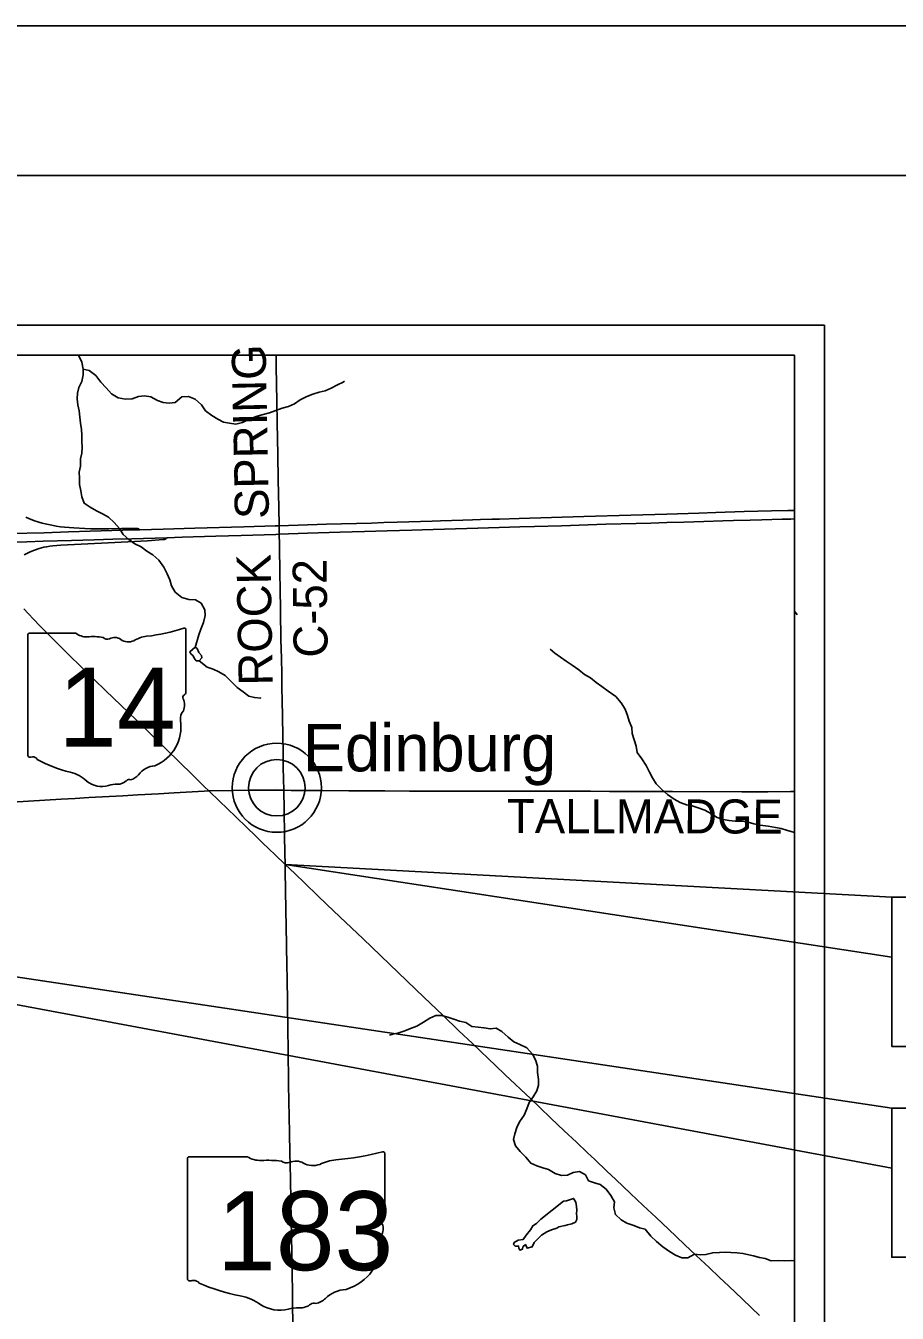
# Model space of a CAD drawing. Extents: x 25.6 to 80.6, y 0.2 to 24.5.
# Drawn here: x 41.848 to 44.756, y 17.932 to 22.23 of the extents above; entities that cross this region are included whole.
import ezdxf

# ---------------------------------------------------------------- set-up
doc = ezdxf.new("R2010")
doc.units = 0
for name, color, linetype in [('GM_X_County_Road', 7, 'Continuous'), ('GM_X_County_Road_Text', 7, 'Continuous'), ('GM_X_Interchange_Ramps', 7, 'Continuous'), ('GM_X_Interstate_Route', 7, 'Continuous'), ('GM_X_Minor_Lake', 7, 'Continuous'), ('GM_X_Minor_River', 7, 'Continuous'), ('GM_X_State_Location', 7, 'Continuous'), ('GM_X_State_Route', 7, 'Continuous'), ('GM_X_State_Shield', 7, 'Continuous'), ('GM_X_Township_Road', 7, 'Continuous'), ('GM_X_Unincorporated', 7, 'Continuous'), ('GM_X_Unincorporated_Location', 7, 'Continuous'), ('GM_X_Unincorporated_Text', 7, 'Continuous'), ('SH_Border', 7, 'Continuous'), ('SH_Cut_Line', 7, 'Continuous'), ('SH_Data', 7, 'Continuous'), ('SH_Text', 7, 'Continuous')]:
    doc.layers.add(name, color=color, linetype=linetype)

msp = doc.modelspace()

# ---------------------------------------------------------------- linework, layer by layer
at = {"layer": 'GM_X_County_Road'}
for points in [[(42.7086, 19.6775), (42.7071, 19.7535), (42.7061, 19.8066), (42.7053, 19.8617), (42.7031, 19.9802), (42.7024, 20.0158), (42.7018, 20.0667), (42.701, 20.1175), (42.6994, 20.1806), (42.6981, 20.2753), (42.6961, 20.3549), (42.6956, 20.3971), (42.6941, 20.4977), (42.6938, 20.5322), (42.6938, 20.5387), (42.6933, 20.5611), (42.6921, 20.622), (42.6898, 20.7139), (42.6887, 20.7971), (42.6879, 20.852), (42.6868, 20.904), (42.6857, 20.9761), (42.6836, 21.093), (42.6832, 21.1303)], [(41.0437, 19.5951), (41.144, 19.6006), (41.1874, 19.603), (41.2197, 19.6047), (41.3686, 19.6136), (41.4381, 19.6175), (41.5399, 19.623), (41.6256, 19.6272), (41.6528, 19.6291), (41.8018, 19.6381), (41.9656, 19.6477), (42.0127, 19.6503), (42.0586, 19.653), (42.1716, 19.6592), (42.2212, 19.6621), (42.2907, 19.6661), (42.3428, 19.6688), (42.443, 19.6746), (42.459, 19.6756)], [(42.459, 19.6756), (42.5364, 19.6767), (42.5926, 19.6776), (42.6484, 19.6777), (42.7086, 19.6775)], [(42.7086, 19.6775), (42.7329, 19.6774), (42.7748, 19.677), (42.8373, 19.6767), (42.9257, 19.6763), (43.046, 19.6756), (43.1282, 19.6752), (43.1941, 19.6751), (43.2986, 19.675), (43.3831, 19.675), (43.4801, 19.6748), (43.5522, 19.6746), (43.618, 19.6744), (43.7324, 19.6743), (43.7958, 19.6741), (43.8678, 19.6739), (43.9276, 19.6739), (44.0059, 19.6732), (44.2371, 19.6729), (44.3241, 19.673), (44.3999, 19.6731), (44.4128, 19.6732)], [(42.7128, 19.4303), (42.7119, 19.4689), (42.7106, 19.525), (42.7101, 19.6121), (42.7086, 19.6775)]]:
    msp.add_lwpolyline(points, dxfattribs=at)
at = {"layer": 'GM_X_Interchange_Ramps'}
for points in [[(42.2286, 20.5475), (42.2265, 20.5494), (42.2249, 20.5503), (42.2231, 20.551), (42.2211, 20.5514), (42.2192, 20.5516), (42.2149, 20.5519), (42.2036, 20.552), (42.1671, 20.5517), (42.1244, 20.551), (42.0834, 20.5507), (42.0648, 20.551), (42.0449, 20.5517), (42.0076, 20.5537), (41.9922, 20.5549), (41.9766, 20.5564), (41.9635, 20.5577), (41.9495, 20.5597), (41.9348, 20.5623), (41.9236, 20.5647), (41.9129, 20.567), (41.9025, 20.5697), (41.8914, 20.573), (41.8845, 20.5752), (41.8772, 20.5777), (41.8687, 20.5809), (41.8598, 20.5842), (41.8474, 20.5895)], [(41.8425, 20.4636), (41.8494, 20.4673), (41.8558, 20.4705), (41.8629, 20.4738), (41.8767, 20.4794), (41.8919, 20.4846), (41.9004, 20.4871), (41.9084, 20.489), (41.9175, 20.491), (41.9277, 20.4926), (41.9382, 20.4939), (41.9512, 20.4953), (41.9642, 20.4961), (42.1231, 20.5042), (42.2534, 20.5105), (42.3066, 20.5145), (42.3089, 20.5149), (42.3111, 20.5155), (42.3127, 20.5161), (42.3147, 20.5171), (42.3158, 20.5178), (42.3169, 20.5188), (42.3183, 20.521)]]:
    msp.add_lwpolyline(points, dxfattribs=at)
at = {"layer": 'GM_X_Interstate_Route'}
for points in [[(41.7951, 20.5346), (41.9095, 20.5377), (41.9902, 20.5402), (42.0623, 20.5424), (42.1717, 20.5457), (42.2286, 20.5475), (42.3059, 20.5499), (42.4115, 20.5528), (42.5756, 20.5576), (42.6799, 20.5607), (42.6933, 20.5611), (42.8514, 20.5659), (43.0018, 20.57), (43.0428, 20.5713), (43.0875, 20.5725), (43.2043, 20.5762), (43.2317, 20.5772), (43.3062, 20.5797), (43.3385, 20.5805), (43.3646, 20.5814), (43.4031, 20.5824), (43.428, 20.5832), (43.4938, 20.5851), (43.6019, 20.5883), (43.71, 20.5917), (43.8666, 20.5964), (43.9872, 20.5999), (44.094, 20.6029), (44.15, 20.6047), (44.245, 20.6079), (44.3362, 20.6106), (44.3909, 20.6116), (44.4128, 20.6119)], [(41.7838, 20.5054), (41.8509, 20.5074), (41.9056, 20.5091), (42, 20.5116), (42.0758, 20.5141), (42.138, 20.5159), (42.2014, 20.5176), (42.3183, 20.521), (42.3691, 20.5228), (42.4064, 20.5239), (42.4824, 20.5261), (42.567, 20.5286), (42.6823, 20.5318), (42.6938, 20.5322), (42.7878, 20.5358), (42.896, 20.5393), (42.978, 20.5414), (43.0538, 20.5436), (43.1358, 20.5463), (43.1706, 20.5473), (43.3557, 20.5526), (43.4278, 20.5548), (43.4962, 20.5567), (43.5458, 20.5584), (43.6353, 20.5611), (43.7832, 20.5657), (43.8851, 20.5685), (43.9336, 20.5697), (43.987, 20.5714), (44.0442, 20.5733), (44.0765, 20.5742), (44.11, 20.5753), (44.1734, 20.5769), (44.2094, 20.5779), (44.2654, 20.5797), (44.3039, 20.5808), (44.3722, 20.5826), (44.4008, 20.5833), (44.4128, 20.5834)]]:
    msp.add_lwpolyline(points, dxfattribs=at)
at = {"layer": 'GM_X_Minor_Lake'}
for p, q in [((42.3983, 20.1335), (42.4061, 20.1261)), ((43.642, 18.3061), (43.5662, 18.2459))]:
    msp.add_line(p, q, dxfattribs=at)
for points in [[(42.4061, 20.1261), (42.4099, 20.1192), (42.4168, 20.1102), (42.4266, 20.1103), (42.4356, 20.1203), (42.434, 20.1279), (42.4256, 20.1377), (42.4193, 20.1513), (42.4125, 20.155), (42.3952, 20.1396), (42.3983, 20.1335)], [(43.5662, 18.2459), (43.552, 18.2312), (43.54, 18.2235), (43.5318, 18.2097), (43.5176, 18.1921), (43.5079, 18.1783), (43.4913, 18.1758), (43.477, 18.1673), (43.4756, 18.1612), (43.4809, 18.1551), (43.4923, 18.156), (43.4931, 18.1485), (43.4962, 18.1424), (43.5053, 18.1456), (43.5067, 18.1532), (43.515, 18.1609), (43.5204, 18.1488), (43.5378, 18.1536), (43.5444, 18.1681), (43.5594, 18.1835), (43.5691, 18.1927), (43.5864, 18.2036), (43.6022, 18.2106), (43.6196, 18.2161), (43.6264, 18.22), (43.6475, 18.2248), (43.6558, 18.2265), (43.6702, 18.2297), (43.6822, 18.2359), (43.6867, 18.2443), (43.6866, 18.2534), (43.6857, 18.2641), (43.6863, 18.2755), (43.6854, 18.2884), (43.6837, 18.3028), (43.676, 18.3148), (43.6526, 18.3069), (43.642, 18.3061)]]:
    msp.add_lwpolyline(points, dxfattribs=at)
at = {"layer": 'GM_X_Minor_River'}
for points in [[(42.0234, 21.1303), (42.0352, 21.1067), (42.0393, 21.0832), (42.0395, 21.0643), (42.0345, 21.0429), (42.0249, 21.023), (42.0205, 21.004), (42.0193, 20.985), (42.0218, 20.9645), (42.0258, 20.9448), (42.0276, 20.9236), (42.0301, 20.9038), (42.0341, 20.8826), (42.0343, 20.8636), (42.0353, 20.8431), (42.0364, 20.8219), (42.0351, 20.8029), (42.0308, 20.7838), (42.0303, 20.7603), (42.026, 20.7397), (42.027, 20.7192), (42.0272, 20.6987), (42.0313, 20.6775), (42.0345, 20.6578), (42.0424, 20.6358), (42.063, 20.6224), (42.0836, 20.6105), (42.1034, 20.6009), (42.124, 20.5897), (42.1431, 20.5717), (42.1608, 20.5514), (42.1724, 20.5318), (42.1915, 20.5146), (42.2122, 20.5004), (42.2327, 20.49), (42.2518, 20.4759), (42.2717, 20.4639), (42.2923, 20.446), (42.3085, 20.4226), (42.3194, 20.4007), (42.328, 20.3803), (42.3343, 20.3606), (42.3459, 20.3395), (42.3688, 20.3208), (42.3916, 20.315), (42.4136, 20.313), (42.4327, 20.3026), (42.4458, 20.28), (42.4468, 20.261), (42.441, 20.2374), (42.4314, 20.216), (42.4256, 20.1969), (42.4134, 20.1545)], [(42.0393, 21.0832), (42.0598, 21.0797), (42.0812, 21.0625), (42.0981, 21.0407), (42.1158, 21.0211), (42.1342, 21.0009), (42.1556, 20.9874), (42.1806, 20.984), (42.2026, 20.985), (42.2237, 20.9921), (42.2441, 20.9946), (42.2654, 20.9911), (42.2875, 20.9785), (42.3065, 20.9726), (42.3262, 20.9698), (42.3459, 20.9723), (42.3684, 20.9909), (42.3903, 20.9919), (42.4132, 20.9831), (42.4346, 20.9651), (42.4477, 20.9448), (42.4684, 20.9291), (42.4882, 20.9164), (42.508, 20.9068), (42.5278, 20.9032), (42.5482, 20.9004), (42.5709, 20.906), (42.595, 20.9177), (42.6199, 20.9271), (42.6395, 20.9327), (42.6607, 20.9375), (42.6825, 20.9454), (42.7029, 20.9533), (42.724, 20.9588), (42.7444, 20.9674), (42.7639, 20.9814), (42.7858, 20.9923), (42.8054, 21.0001), (42.8265, 21.0065), (42.8469, 21.0113), (42.8665, 21.0206), (42.8876, 21.0308), (42.9071, 21.0401), (42.9109, 21.0432)], [(44.4128, 19.5373), (44.4098, 19.538), (44.39, 19.5438), (44.368, 19.5496), (44.349, 19.5539), (44.3254, 19.5574), (44.2989, 19.5609), (44.2769, 19.5652), (44.2579, 19.571), (44.2381, 19.5746), (44.2154, 19.575), (44.1949, 19.5763), (44.1744, 19.5806), (44.1554, 19.5872), (44.1356, 19.5991), (44.1142, 19.6118), (44.0914, 19.6191), (44.0716, 19.6257), (44.0527, 19.6292), (44.0313, 19.6373), (44.0115, 19.6477), (43.9894, 19.6634), (43.9702, 19.6806), (43.9511, 19.6994), (43.9395, 19.719), (43.9294, 19.7386), (43.9185, 19.7605), (43.9031, 19.7831), (43.8877, 19.8042), (43.8844, 19.8246), (43.8774, 19.8458), (43.8718, 19.867), (43.87, 19.8875), (43.8615, 19.9079), (43.8559, 19.9276), (43.8481, 19.948), (43.8342, 19.9699), (43.8165, 19.9909), (43.7913, 20.0081), (43.7699, 20.0245), (43.7508, 20.0372), (43.7317, 20.0529), (43.7127, 20.0641), (43.6928, 20.0798), (43.6714, 20.0955), (43.6515, 20.1089), (43.6133, 20.1358), (43.598, 20.1485)], [(42.4266, 20.1103), (42.4534, 20.0886), (42.4732, 20.0821), (42.4922, 20.0732), (42.5128, 20.0605), (42.5534, 20.0208), (42.5733, 20.0058), (42.5924, 19.9916), (42.6114, 19.9873), (42.6319, 19.9853), (42.6296, 19.9875)], [(43.3571, 18.8867), (43.3366, 18.8887), (43.316, 18.9021), (43.2955, 18.9072), (43.2757, 18.9138), (43.2559, 18.9204), (43.2354, 18.9254), (43.2157, 18.9252), (43.1961, 18.9166), (43.1751, 18.9034), (43.1525, 18.8902), (43.1321, 18.8824), (43.1125, 18.8745), (43.0929, 18.8682), (43.0725, 18.8634), (43.062, 18.8595)], [(44.4128, 18.1068), (44.4034, 18.1074), (44.3799, 18.1071), (44.3587, 18.1076), (44.3352, 18.1065), (44.3147, 18.1139), (44.2957, 18.1182), (44.2759, 18.1233), (44.241, 18.1312), (44.2213, 18.1332), (44.2008, 18.1345), (44.1818, 18.1358), (44.1622, 18.1348), (44.1402, 18.1337), (44.1176, 18.1274), (44.0979, 18.1271), (44.0789, 18.1284), (44.0571, 18.1168), (44.0366, 18.1165), (44.0161, 18.1254), (43.9955, 18.138), (43.9733, 18.1537), (43.9527, 18.1709), (43.9335, 18.1889), (43.9143, 18.2122), (43.8953, 18.2165), (43.8763, 18.2247), (43.8534, 18.2327), (43.8344, 18.2439), (43.8152, 18.2611), (43.8097, 18.2838), (43.8125, 18.3036), (43.8001, 18.3247), (43.7847, 18.3458), (43.7648, 18.3615), (43.7458, 18.3666), (43.726, 18.374), (43.7152, 18.3936), (43.6954, 18.4047), (43.6749, 18.4014), (43.6553, 18.3928), (43.6357, 18.3911), (43.6144, 18.3984), (43.5922, 18.4118), (43.5732, 18.4169), (43.5527, 18.4235), (43.5329, 18.4323), (43.5168, 18.4526), (43.4976, 18.4714), (43.4815, 18.4909), (43.4752, 18.5114), (43.4795, 18.5304), (43.486, 18.5518), (43.4957, 18.5709), (43.5113, 18.5931), (43.5194, 18.6145), (43.5275, 18.6351), (43.5409, 18.6542), (43.5535, 18.6742), (43.5586, 18.6932), (43.5591, 18.7122), (43.5558, 18.735), (43.5556, 18.757), (43.5492, 18.7774), (43.5392, 18.797), (43.52, 18.8181), (43.4964, 18.8284), (43.4766, 18.838), (43.4574, 18.8538), (43.4368, 18.8725), (43.4177, 18.8829), (43.398, 18.8811), (43.3768, 18.8847), (43.3571, 18.8867)]]:
    msp.add_lwpolyline(points, dxfattribs=at)
at = {"layer": 'GM_X_State_Route'}
for points in [[(41.8408, 20.2836), (41.8564, 20.2671), (41.8734, 20.2492), (41.8956, 20.2258), (41.9209, 20.2004), (41.9694, 20.1517)], [(41.9694, 20.1517), (41.9951, 20.126), (42.0289, 20.0929), (42.0775, 20.0465), (42.1143, 20.0113), (42.2169, 19.9118), (42.2198, 19.9091)], [(42.2198, 19.9091), (42.3095, 19.8216), (42.3671, 19.7649), (42.3958, 19.7373), (42.4389, 19.6952)], [(42.4389, 19.6952), (42.4447, 19.6896), (42.459, 19.6756), (42.4953, 19.64), (42.5185, 19.6175), (42.5831, 19.5555), (42.6162, 19.5236), (42.6379, 19.5027)], [(42.6379, 19.5027), (42.6799, 19.4625), (42.7128, 19.4303)], [(42.7128, 19.4303), (42.7453, 19.3995), (42.7802, 19.3659), (42.8214, 19.3262), (42.8527, 19.296), (42.8959, 19.2548), (42.9737, 19.1814), (43.0902, 19.0695), (43.1771, 18.9858), (43.2389, 18.9264), (43.293, 18.875), (43.3382, 18.8324), (43.3641, 18.8073), (43.3918, 18.781)], [(42.7406, 17.7303), (42.7405, 17.7348), (42.7396, 17.7946), (42.7387, 17.8812), (42.7378, 17.976), (42.7363, 18.0903), (42.7345, 18.1848), (42.7325, 18.3068), (42.7307, 18.3811), (42.7294, 18.4657), (42.7275, 18.534), (42.7248, 18.6943), (42.7233, 18.8161), (42.7222, 18.8744), (42.7208, 18.9664), (42.7195, 19.0521), (42.7188, 19.0882), (42.7177, 19.1628), (42.716, 19.2796), (42.7133, 19.4075), (42.7128, 19.4303)], [(43.3918, 18.781), (43.4137, 18.7603), (43.4479, 18.7277), (43.5331, 18.6477), (43.5634, 18.6183), (43.5998, 18.5826), (43.6444, 18.5411), (43.6852, 18.5029), (43.722, 18.4676), (43.7464, 18.4446), (43.787, 18.4063), (43.8169, 18.3782), (43.8653, 18.3318), (43.9079, 18.2918), (43.9514, 18.2509), (43.9921, 18.2126), (44.0463, 18.1614), (44.0851, 18.1246), (44.1277, 18.0846), (44.1629, 18.0513), (44.1937, 18.0223), (44.2387, 17.9795), (44.2691, 17.9501), (44.2962, 17.9245)]]:
    msp.add_lwpolyline(points, dxfattribs=at)
at = {"layer": 'GM_X_State_Shield'}
for p, q in [((42.382, 20.0032), (42.382, 20.2126)), ((41.8547, 20.1958), (41.8547, 19.7955)), ((42.0143, 20.2027), (41.8599, 20.2027)), ((42.382, 20.0033), (42.382, 20.0032)), ((42.387, 18.4473), (42.387, 18.0471)), ((42.5865, 18.4542), (42.3935, 18.4542)), ((43.0462, 18.2547), (43.0462, 18.4641)), ((43.0461, 18.2548), (43.0462, 18.2547))]:
    msp.add_line(p, q, dxfattribs=at)
for centre, radius, start, end in [((42.1942, 20.7483), 0.5592, 275.8445, 288.9065), ((42.3762, 20.2135), 0.00587, 351.8621, 97.738), ((41.8607, 20.1966), 0.00611, 98.1301, 188.1301), ((42.0511, 20.2491), 0.0593, 231.6195, 271.1119), ((42.0708, 19.978), 0.2127, 80.4867, 94.9883), ((42.119, 20.1987), 0.0171, 219.7921, 297.1024), ((42.1441, 20.1524), 0.0355, 54.4667, 119.1411), ((42.19, 20.2159), 0.0428, 233.8562, 294.8282), ((42.2655, 20.0804), 0.1125, 97.3462, 120.7689), ((42.3807, 19.9878), 0.00909, 107.944, 210.337), ((42.3758, 20.0024), 0.00628, 289.6038, 7.7341), ((42.3229, 19.9614), 0.0545, 340.033, 23.6496), ((42.2255, 19.889), 0.1399, 292.3089, 8.9858), ((42.4031, 19.9156), 0.0397, 136.8065, 186.9296), ((41.8608, 19.7947), 0.00616, 171.9584, 258.3066), ((41.8617, 19.8356), 0.047, 267.339, 280.6039), ((41.8714, 19.7724), 0.017, 29.7484, 93.2717), ((42.0855, 20.132), 0.4038, 240.4129, 257.1985), ((41.9651, 19.6157), 0.1264, 47.1842, 75.836), ((42.2845, 19.6832), 0.0766, 94.4031, 142.5768), ((42.1017, 19.7705), 0.0802, 230.7004, 286.2918), ((42.1481, 19.6321), 0.0659, 85.6951, 111.2099), ((42.1539, 19.7405), 0.0427, 268.777, 315.5493), ((42.1926, 19.7017), 0.012, 65.7517, 132.6484), ((42.1874, 19.7567), 0.0452, 282.8732, 323.2771)]:
    msp.add_arc(centre, radius, start, end, dxfattribs=at)
for centre, major_axis, start_param, end_param in [((42.3946, 18.4482), (0.00764, 0), 1.712693, 3.28349), ((42.6325, 18.5007), (0.0741, 0), 4.042523, 4.731795), ((42.6571, 18.2295), (0.2659, 0), 1.404758, 1.657858), ((42.7488, 18.404), (0.0444, 0), 0.950623, 2.079405), ((42.9005, 18.332), (0.1406, 0), 1.699011, 2.107814), ((42.8114, 18.9999), (0.699, 0), 4.814394, 5.042369), ((43.0389, 18.465), (0.00734, 0), 6.141152, 7.989035), ((42.7174, 18.4502), (0.0214, 0), 3.836095, 5.185415), ((42.8061, 18.4674), (0.0534, 0), 4.081561, 5.145723), ((43.0445, 18.2394), (0.0114, 0), 1.883978, 3.671073), ((42.9722, 18.2129), (0.0682, 0), 5.934695, 6.695948), ((43.0383, 18.2539), (0.00785, 0), 5.05454, 6.418171), ((43.0725, 18.1671), (0.0496, 0), 2.387724, 3.262537), ((42.8505, 18.1405), (0.1748, 0), 5.101752, 6.440018), ((42.3946, 18.0462), (0.0077, 0), 3.00124, 4.508301), ((42.3958, 18.0871), (0.0588, 0), 4.665946, 4.897461), ((42.4078, 18.024), (0.0212, 0), 0.519207, 1.627899), ((42.6755, 18.3836), (0.5048, 0), 4.195997, 4.488961), ((42.525, 17.8673), (0.1579, 0), 0.823519, 1.323587), ((42.8029, 18.0083), (0.0565, 0), 4.937069, 5.64225), ((42.9242, 17.9347), (0.0958, 0), 1.647645, 2.488434), ((42.6958, 18.022), (0.1002, 0), 4.026481, 4.996735), ((42.7537, 17.8836), (0.0824, 0), 1.495662, 1.94098), ((42.761, 17.992), (0.0534, 0), 4.691044, 5.507374), ((42.8093, 17.9533), (0.015, 0), 1.147584, 2.315152)]:
    msp.add_ellipse(centre, major_axis=major_axis, ratio=0.8, start_param=start_param, end_param=end_param, dxfattribs=at)
at = {"layer": 'GM_X_Township_Road'}
msp.add_line((44.4128, 20.276), (44.4213, 20.2636), dxfattribs=at)
at = {"layer": 'GM_X_Unincorporated'}
for radius in [0.1488, 0.0943]:
    msp.add_circle((42.6853, 19.6861), radius, dxfattribs=at)
at = {"layer": 'GM_X_Unincorporated_Location'}
msp.add_line((42.6853, 19.6861), (42.6853, 19.6861), dxfattribs=at)
at = {"layer": 'SH_Border'}
msp.add_lwpolyline([(37.0128, 21.7303), (69.0128, 21.7303), (69.0128, 0.7303), (37.0128, 0.7303)], close=True, dxfattribs=at)
at = {"layer": 'SH_Cut_Line'}
msp.add_lwpolyline([(35.5128, 0.2303), (69.5128, 0.2303), (69.5128, 22.2303), (35.5128, 22.2303)], close=True, dxfattribs=at)
at = {"layer": 'SH_Data'}
for p, q in [((37.5128, 21.2303), (44.5128, 21.2303)), ((44.5128, 21.2303), (44.5128, 17.8303)), ((37.6128, 21.1303), (44.4128, 21.1303)), ((37.6128, 21.1303), (44.4128, 21.1303)), ((44.4128, 21.1303), (44.4128, 14.3303))]:
    msp.add_line(p, q, dxfattribs=at)
at = {"layer": 'SH_Text'}
for points in [[(37.6128, 21.1303), (44.4128, 21.1303), (44.4128, 14.3303), (37.6128, 14.3303)], [(37.6128, 21.1303), (44.4128, 21.1303), (44.4128, 14.3303), (37.6128, 14.3303)], [(41.0128, 17.7303), (44.4128, 17.7303), (44.4128, 21.1303), (41.0128, 21.1303)], [(41.0128, 17.7303), (44.4128, 17.7303), (44.4128, 21.1303), (41.0128, 21.1303)], [(44.7372, 18.6163), (44.7372, 18.4163), (39.3128, 19.4303)], [(44.7372, 19.3204), (44.7372, 19.1204), (42.7128, 19.4303)], [(47.5713, 19.3204), (44.7372, 19.3204), (44.7372, 18.8225), (47.5713, 18.8225)], [(47.5713, 18.6163), (44.7372, 18.6163), (44.7372, 18.1184), (47.5713, 18.1184)]]:
    msp.add_lwpolyline(points, close=True, dxfattribs=at)

# ---------------------------------------------------------------- texts
at = {"layer": 'GM_X_County_Road_Text'}
for s, rotation, p in [('SPRING', 91.1153, (42.6595, 20.5846)), ('ROCK', 90.9794, (42.6718, 20.0281)), ('C-52', 90.6889, (42.8554, 20.1212)), ('TALLMADGE', 359.8901, (43.4533, 19.5348))]:
    msp.add_text(s, height=0.11364, rotation=rotation, dxfattribs=at).set_placement(p)
at = {"layer": 'GM_X_State_Location'}
for s in ['s', 'r']:
    msp.add_text(s, height=0.000379, dxfattribs=at).set_placement((42.1124, 19.9691))
msp.add_text('14', height=0.000379, rotation=0, dxfattribs=at).set_placement((42.017, 19.9415))
at = {"layer": 'GM_X_State_Shield'}
for s, p in [('14', (41.9559, 19.8238)), ('183', (42.4859, 18.0753))]:
    msp.add_text(s, height=0.26367, dxfattribs=at).set_placement(p)
at = {"layer": 'GM_X_Unincorporated_Text'}
msp.add_text('Edinburg', height=0.15795, rotation=0, dxfattribs=at).set_placement((42.772, 19.7408))

doc.saveas('drawing.dxf')
